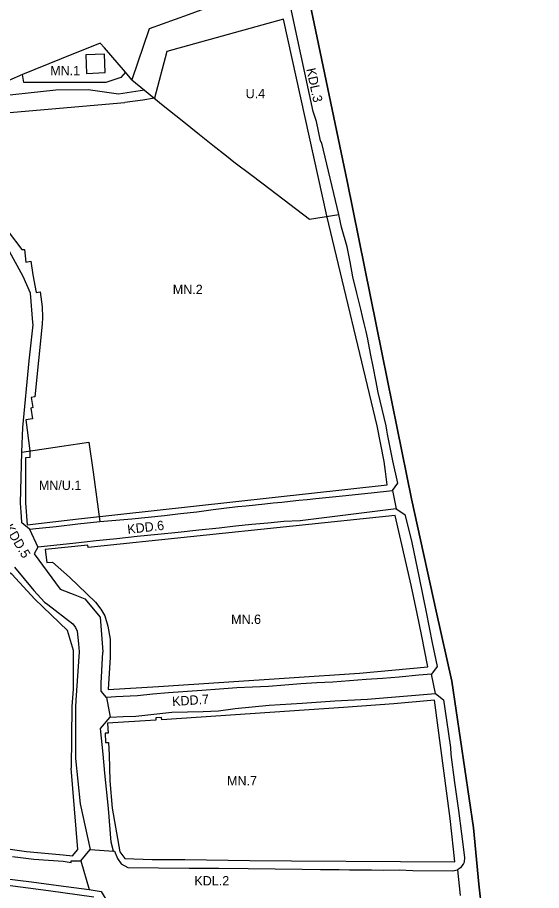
# Model space of a CAD drawing. Extents: x 7423274 to 7424514, y 5542390 to 5544261.
# Drawn here: x 7424007.3 to 7424231.1, y 5543609.4 to 5543982.5 of the extents above; entities that cross this region are included whole.
import ezdxf

# ---------------------------------------------------------------- set-up
doc = ezdxf.new("R2010")
doc.units = 0
for name, color, linetype in [('granica obszaru objętego planem', 7, 'Continuous'), ('LIN_Granica Planu', 7, 'Continuous'), ('linie rozgraniczające tereny o różnym przeznaczeniu lub różnych zasadach zagospodarowania', 7, 'Continuous'), ('nieprzekraczalna linia zabudowy', 7, 'Continuous'), ('oznaczenia terenów', 7, 'Continuous')]:
    doc.layers.add(name, color=color, linetype=linetype)

msp = doc.modelspace()

# ---------------------------------------------------------------- linework, layer by layer
at = {"layer": 'granica obszaru objętego planem'}
for p, q in [((7424131.7, 5543990.87), (7424133.97, 5543980.01)), ((7424133.97, 5543980.01), (7424148.11, 5543912.49)), ((7424148.11, 5543912.49), (7424163.08, 5543838.56)), ((7424163.08, 5543838.56), (7424169.46, 5543807.01)), ((7424169.46, 5543807.01), (7424175.57, 5543776.81)), ((7424175.57, 5543776.81), (7424186.15, 5543728.82)), ((7424186.15, 5543728.82), (7424192.74, 5543698.89)), ((7424204.36, 5543612.15), (7424228.15, 5543398.17))]:
    msp.add_line(p, q, dxfattribs=at)
msp.add_lwpolyline([(7424192.74, 5543698.89), (7424202.07, 5543636.25), (7424204.36, 5543612.15)], dxfattribs=at)
at = {"layer": 'LIN_Granica Planu'}
for p, q in [((7424133.97, 5543980.01), (7424131.7, 5543990.87)), ((7424148.11, 5543912.49), (7424133.97, 5543980.01)), ((7424163.08, 5543838.56), (7424148.11, 5543912.49)), ((7424169.46, 5543807.01), (7424163.08, 5543838.56)), ((7424175.57, 5543776.81), (7424169.46, 5543807.01)), ((7424186.15, 5543728.82), (7424175.57, 5543776.81)), ((7424192.74, 5543698.89), (7424186.15, 5543728.82)), ((7424228.15, 5543398.17), (7424204.36, 5543612.15))]:
    msp.add_line(p, q, dxfattribs=at)
msp.add_lwpolyline([(7424204.36, 5543612.15), (7424202.07, 5543636.25), (7424192.74, 5543698.89)], dxfattribs=at)
at = {"layer": 'linie rozgraniczające tereny o różnym przeznaczeniu lub różnych zasadach zagospodarowania'}
for p, q in [((7424167.46, 5543780.3), (7424169.1, 5543772.52)), ((7424012.43, 5543763.83), (7424016.04, 5543756.19)), ((7424045.38, 5543691.93), (7424046.98, 5543683.5)), ((7424034.43, 5543622.13), (7424038.33, 5543626.9)), ((7424038.33, 5543626.9), (7424048.4, 5543626.15)), ((7424034.43, 5543622.13), (7424037.96, 5543609.76)), ((7424195.16, 5543618.28), (7424196.31, 5543607.23))]:
    msp.add_line(p, q, dxfattribs=at)
for points in [[(7424129.39, 5544001.9), (7424129.8, 5543999.91), (7424131.7, 5543990.87), (7424133.97, 5543980.01), (7424148.11, 5543912.49), (7424163.08, 5543838.56), (7424169.46, 5543807.01), (7424175.57, 5543776.81), (7424186.15, 5543728.82), (7424192.74, 5543698.89), (7424202.07, 5543636.25), (7424204.36, 5543612.15), (7424228.15, 5543398.17), (7424228.51, 5543394.73), (7424242.62, 5543256.86), (7424248.04, 5543257.08)], [(7424121.12, 5543998.85), (7424109.29, 5543994.26), (7424106.54, 5543993.26), (7424101.71, 5543991.49), (7424096.89, 5543989.71), (7424080.24, 5543983.67), (7424063.58, 5543977.62), (7424056.19, 5543955.82)], [(7424144.55, 5543898.27), (7424137.31, 5543928.84), (7424136.75, 5543929.79), (7424134.98, 5543938), (7424133.54, 5543942.33), (7424128.46, 5543966.1), (7424122.6, 5543993.46), (7424121.12, 5543998.85)], [(7424053.47, 5543959.08), (7424044.49, 5543969.61), (7424042.6, 5543971.47), (7424026.04, 5543964.79), (7424009.49, 5543958.12)], [(7424053.47, 5543959.08), (7424051.5, 5543956.89), (7424045.13, 5543954.76), (7424027.61, 5543954.73), (7424010.09, 5543954.7), (7424009.49, 5543958.12)], [(7424056.19, 5543955.82), (7424053.47, 5543959.08)], [(7424009.49, 5543958.12), (7424003.59, 5543955.61), (7423997.7, 5543953.09), (7423992.95, 5543951.78), (7423988.2, 5543950.47), (7423983.6, 5543948.86), (7423979, 5543947.24), (7423974.12, 5543945.83), (7423962.62, 5543942.75), (7423956.01, 5543941.1), (7423942.79, 5543937.91), (7423929.57, 5543934.71), (7423925.31, 5543933.4), (7423921.74, 5543931.7), (7423920.97, 5543931.26)], [(7424056.19, 5543955.82), (7424061.6, 5543951.39)], [(7424061.6, 5543951.39), (7424050.54, 5543949.78), (7424037.51, 5543951.62), (7424023.67, 5543951.43), (7424011.93, 5543950.16), (7424001.33, 5543948.98), (7423995.7, 5543948.35), (7423987.33, 5543944.28), (7423981.88, 5543941.81), (7423950.16, 5543934.53), (7423925.71, 5543928.9), (7423925.33, 5543927.63), (7423925.33, 5543927.61), (7423925.32, 5543927.6), (7423925.28, 5543927.6)], [(7424061.6, 5543951.39), (7424069.62, 5543944.95), (7424077.63, 5543938.51), (7424085.03, 5543932.56), (7424090.79, 5543927.96), (7424096.55, 5543923.36), (7424099.78, 5543920.77), (7424107.52, 5543914.96), (7424115.25, 5543909.14), (7424123.62, 5543902.75), (7424131.99, 5543896.36), (7424138.27, 5543897.32), (7424144.55, 5543898.27)], [(7424009.26, 5543796.75), (7424009.59, 5543807.35), (7424012.28, 5543835.77), (7424014.01, 5543851.2), (7424013.93, 5543852.09), (7424012.86, 5543864.73), (7424009.71, 5543871.85), (7424004, 5543882.5), (7423992.6, 5543894.18), (7423987.31, 5543898.3), (7423984.61, 5543899.85), (7423973.32, 5543904.78), (7423938.39, 5543918.19), (7423926.52, 5543923.51), (7423925.07, 5543926.76), (7423925.28, 5543927.6)], [(7424167.46, 5543780.3), (7424169.79, 5543783.54), (7424167.62, 5543793.09), (7424165.29, 5543804.44), (7424165.04, 5543806.21), (7424164.8, 5543807.99), (7424161.42, 5543822.2), (7424160.36, 5543827.44), (7424159.3, 5543832.67), (7424158.15, 5543838.86), (7424157, 5543845.04), (7424156.21, 5543848.36), (7424155.41, 5543851.67), (7424154.67, 5543854.73), (7424153.94, 5543857.79), (7424152.24, 5543864.71), (7424150.53, 5543871.63), (7424149.33, 5543878.09), (7424148.12, 5543884.55), (7424145.68, 5543892.86), (7424144.55, 5543898.27)], [(7424009.26, 5543796.75), (7424026.29, 5543799.32), (7424037.82, 5543801.07), (7424039.6, 5543788.22), (7424041.04, 5543777.69), (7424042.47, 5543767.15)], [(7424012.43, 5543763.83), (7424009.19, 5543766.54), (7424009, 5543769.26), (7424008.58, 5543775.01), (7424009.26, 5543796.75)], [(7424042.47, 5543767.15), (7424049.32, 5543767.73), (7424056.17, 5543768.31), (7424063.11, 5543769.01), (7424070.05, 5543769.72), (7424076.99, 5543770.51), (7424083.92, 5543771.3), (7424090.84, 5543772.19), (7424097.77, 5543773.07), (7424101.4, 5543773.45), (7424105.03, 5543773.83), (7424108.98, 5543774.24), (7424112.93, 5543774.65), (7424116.56, 5543775.03), (7424120.19, 5543775.41), (7424123.82, 5543775.79), (7424127.45, 5543776.16), (7424131.08, 5543776.54), (7424134.71, 5543776.92), (7424140.43, 5543777.51), (7424146.15, 5543778.11), (7424158.3, 5543779.36), (7424167.46, 5543780.3)], [(7424169.1, 5543772.52), (7424128.11, 5543767.46), (7424121.04, 5543767.13), (7424114.2, 5543766.46), (7424107.36, 5543765.79), (7424100.41, 5543765.04), (7424093.46, 5543764.3), (7424084.71, 5543763.38), (7424075.97, 5543762.47), (7424067.21, 5543761.55), (7424058.46, 5543760.64), (7424049.71, 5543759.73), (7424040.96, 5543758.81), (7424035.96, 5543758.29), (7424030.97, 5543757.76), (7424016.04, 5543756.19)], [(7424169.1, 5543772.52), (7424172.72, 5543770.15), (7424173.85, 5543765.62), (7424175.7, 5543758.17), (7424177.25, 5543750.58), (7424178.79, 5543742.98), (7424181.78, 5543728.31), (7424184.45, 5543715.25), (7424186.51, 5543705.14), (7424184.11, 5543701.89)], [(7424012.43, 5543763.83), (7424016.61, 5543764.26), (7424023.81, 5543765.01), (7424033.14, 5543766.08), (7424042.47, 5543767.15)], [(7424016.04, 5543756.19), (7424014.43, 5543753.22), (7424025.52, 5543738.19), (7424031.86, 5543735.73), (7424036.13, 5543734.08), (7424042.68, 5543726.25), (7424043.77, 5543711.35)], [(7424006.1, 5543747.6), (7424014.31, 5543737.6), (7424018.89, 5543732.62), (7424020.25, 5543731.58), (7424031, 5543723.4), (7424032.09, 5543721.82), (7424032.78, 5543720.24), (7424033.42, 5543714.89), (7424033.72, 5543711.43), (7424032.26, 5543690.72), (7424032.15, 5543687.75), (7424032.14, 5543665.88), (7424034.16, 5543646.49), (7424038.33, 5543626.9)], [(7424045.38, 5543691.93), (7424043.11, 5543694.66), (7424043.14, 5543697.97), (7424043.77, 5543711.24)], [(7424043.76, 5543711.35), (7424043.77, 5543711.24)], [(7424043.77, 5543711.35), (7424043.77, 5543711.24)], [(7424184.11, 5543701.89), (7424178.68, 5543701.37), (7424170.25, 5543700.55), (7424163.25, 5543700.05), (7424156.24, 5543699.55), (7424149.12, 5543699.02), (7424141.99, 5543698.49), (7424135.17, 5543698.09), (7424128.35, 5543697.69), (7424121.44, 5543697.11), (7424114.52, 5543696.53), (7424107.76, 5543696.28), (7424101, 5543696.02), (7424093.55, 5543695.46), (7424086.1, 5543694.91), (7424071.79, 5543693.85), (7424065.17, 5543693.25), (7424058.56, 5543692.66), (7424049.29, 5543692.12), (7424045.38, 5543691.93)], [(7424185.8, 5543693.62), (7424184.11, 5543701.89)], [(7424046.98, 5543683.5), (7424052.41, 5543683.7), (7424057.83, 5543683.89), (7424065.51, 5543684.72), (7424073.19, 5543685.55), (7424079.9, 5543685.75), (7424086.6, 5543685.96), (7424093.11, 5543686.17), (7424100.35, 5543687.16), (7424107.57, 5543687.9), (7424114.79, 5543688.64), (7424128.88, 5543689.51), (7424142.81, 5543690.39), (7424156.75, 5543691.22), (7424170.42, 5543692.3), (7424185.8, 5543693.62)], [(7424185.8, 5543693.62), (7424189.23, 5543690.91), (7424190.53, 5543682.18), (7424192.27, 5543670.48), (7424192.38, 5543667.53), (7424193.99, 5543655.56), (7424195.6, 5543643.59), (7424196.88, 5543633.58), (7424198.17, 5543623.57), (7424198.09, 5543621.51), (7424197.8, 5543620.87), (7424196.51, 5543619.05), (7424195.16, 5543618.28)], [(7424048.4, 5543626.15), (7424047.38, 5543630.11), (7424046.14, 5543644.41), (7424044.69, 5543659.51), (7424043.99, 5543667.73), (7424042.82, 5543678.7), (7424046.98, 5543683.5)], [(7424005.18, 5543623.99), (7424014.28, 5543622.79), (7424020.58, 5543622.35), (7424026.87, 5543621.91), (7424030.26, 5543621.38), (7424030.33, 5543622.09), (7424034.43, 5543622.13)], [(7424048.4, 5543626.15), (7424048.75, 5543626.21), (7424050.01, 5543623.14), (7424051.64, 5543620.81), (7424054.53, 5543619.28), (7424067.57, 5543619.15), (7424080.6, 5543619.01), (7424093.25, 5543618.88), (7424105.91, 5543618.75), (7424117.38, 5543618.63), (7424128.85, 5543618.51), (7424136.76, 5543618.42), (7424144.67, 5543618.34), (7424149.07, 5543618.29), (7424153.47, 5543618.23), (7424158.46, 5543618.17), (7424163.46, 5543618.12), (7424170.32, 5543618.16), (7424176.1, 5543617.96), (7424193.29, 5543617.86), (7424195.16, 5543618.28)], [(7424054.53, 5543619.28), (7424054.53, 5543619.28)], [(7424001.65, 5543614.58), (7424013.28, 5543613.04), (7424024.91, 5543611.49), (7424031.44, 5543610.62), (7424037.96, 5543609.76)], [(7424037.96, 5543609.76), (7424043.11, 5543608.99), (7424044.74, 5543606.11), (7424046.74, 5543601.68), (7424048.53, 5543597), (7424049.9, 5543593.66)]]:
    msp.add_lwpolyline(points, dxfattribs=at)
at = {"layer": 'nieprzekraczalna linia zabudowy'}
for p, q in [((7424139.5, 5543897.79), (7424120.89, 5543981.86)), ((7424044.46, 5543966.91), (7424036.52, 5543966.55)), ((7424036.52, 5543966.55), (7424036.88, 5543958.64)), ((7424044.83, 5543959.01), (7424044.46, 5543966.91)), ((7424036.88, 5543958.64), (7424044.83, 5543959.01)), ((7424163.96, 5543792.72), (7424160.98, 5543807.93)), ((7424164.5, 5543788.52), (7424163.96, 5543792.72)), ((7424165.23, 5543782.83), (7424164.5, 5543788.52)), ((7424051.02, 5543625.94), (7424053.16, 5543623.07))]:
    msp.add_line(p, q, dxfattribs=at)
for points in [[(7424120.89, 5543981.86), (7424071.1, 5543967.94), (7424065.86, 5543947.97)], [(7424065.86, 5543947.97), (7424065.86, 5543947.97), (7424060.91, 5543947.25), (7424053.23, 5543946.13)], [(7424053.24, 5543946.06), (7424053.24, 5543946.06), (7424053.24, 5543946.06), (7424053.24, 5543946.06), (7423982.54, 5543939.91), (7423960.7, 5543934.36)], [(7423950.39, 5543919.32), (7423963.48, 5543914.06), (7423967.18, 5543912.57), (7423970.64, 5543911.16), (7423976.27, 5543908.88), (7423981.11, 5543906.98), (7423985.86, 5543904.69), (7423988.77, 5543903.12), (7423991.47, 5543901.48), (7423993.9, 5543899.86), (7423996.01, 5543898.27), (7423998.22, 5543896.33), (7424000.76, 5543893.82), (7424003.4, 5543891), (7424009.18, 5543883.33), (7424009.18, 5543883.33), (7424010.28, 5543883.42), (7424010.92, 5543877.97), (7424013, 5543878.3), (7424013.93, 5543872.51), (7424015.35, 5543865.04), (7424017.04, 5543865.32), (7424017.82, 5543858.83), (7424018.03, 5543854.34)], [(7424160.98, 5543807.93), (7424139.5, 5543897.79), (7424139.5, 5543897.79), (7424139.5, 5543897.79)], [(7424018.03, 5543854.34), (7424017.95, 5543851.41), (7424014.81, 5543820.41)], [(7424014.81, 5543820.41), (7424013.16, 5543820.11), (7424013.88, 5543815.76), (7424013.04, 5543815.59), (7424013.82, 5543810.96), (7424010.91, 5543810.52), (7424012.58, 5543797.24)], [(7424012.58, 5543797.24), (7424012.55, 5543794.42), (7424010.75, 5543794.25), (7424010.78, 5543775.14), (7424011.41, 5543765.69)], [(7424011.41, 5543765.69), (7424033.44, 5543768.26), (7424165.23, 5543782.83)], [(7424168.61, 5543769.66), (7424037.5, 5543756.04), (7424037.37, 5543756.92)], [(7424182.6, 5543704.96), (7424179.8, 5543718.84), (7424177.97, 5543727.84), (7424175.39, 5543739.93), (7424168.61, 5543769.66)], [(7424037.37, 5543756.92), (7424037.37, 5543756.92), (7424019.23, 5543755.11)], [(7424019.23, 5543755.11), (7424019.82, 5543749.54), (7424022.31, 5543749.74), (7424029.52, 5543743.26), (7424040.7, 5543732.62), (7424042.95, 5543729.69), (7424044.64, 5543726.76), (7424045.95, 5543722.32), (7424046.97, 5543716.83), (7424046.88, 5543709.16), (7424046.09, 5543695.27)], [(7424028.68, 5543720.51), (7424014.7, 5543733.87), (7424004.92, 5543744.63), (7424003.52, 5543745.44)], [(7424031.21, 5543695.46), (7424031.21, 5543711.91), (7424028.68, 5543720.51)], [(7424046.09, 5543695.27), (7424067.6, 5543696.63), (7424123.28, 5543700.24), (7424153.32, 5543702.22), (7424182.6, 5543704.96)], [(7424030.37, 5543661.69), (7424030.71, 5543687.98), (7424031.21, 5543695.46)], [(7424185.46, 5543690.76), (7424168.07, 5543689.2), (7424146.57, 5543687.62), (7424068.91, 5543682.37)], [(7424194.09, 5543621.69), (7424193.51, 5543627.08), (7424192.14, 5543640.18), (7424185.46, 5543690.76)], [(7424066.43, 5543682.25), (7424045.77, 5543680.94)], [(7424068.91, 5543682.37), (7424068.86, 5543683.3), (7424066.38, 5543683.17), (7424066.43, 5543682.25)], [(7424045.77, 5543680.94), (7424046.01, 5543676.67), (7424044.77, 5543676.6), (7424044.99, 5543672.61), (7424046.26, 5543672.68), (7424046.55, 5543667.36)], [(7424046.56, 5543667.42), (7424046.71, 5543656.21)], [(7424026.85, 5543624.64), (7424030.85, 5543624.21), (7424033.07, 5543626.99), (7424030.22, 5543661.65)], [(7424046.71, 5543656.21), (7424047.76, 5543644.59), (7424051.02, 5543625.94)], [(7423837.7, 5543649.44), (7423872.04, 5543646.02), (7424011.15, 5543626.09), (7424026.85, 5543624.64)], [(7424039.93, 5543606.59), (7424020.52, 5543609.24), (7423987.89, 5543613.53), (7423960.85, 5543617.16), (7423923.09, 5543622.46), (7423913.13, 5543624.02), (7423890.12, 5543627.03)], [(7424053.16, 5543623.07), (7424064.89, 5543622.65), (7424069.82, 5543622.62), (7424078.85, 5543622.68), (7424106.5, 5543622.21), (7424124.31, 5543622.12), (7424170.95, 5543621.83), (7424194.09, 5543621.69)]]:
    msp.add_lwpolyline(points, dxfattribs=at)

# ---------------------------------------------------------------- texts
at = {"layer": 'oznaczenia terenów'}
for s, p in [('MN.1', (7424021.31, 5543957.84)), ('U.4', (7424104.78, 5543948.01)), ('MN.2', (7424073.66, 5543864.29)), ('MN/U.1', (7424016.48, 5543780.6)), ('MN.6', (7424098.56, 5543723.32)), ('MN.7', (7424096.83, 5543654.28)), ('KDL.2', (7424082.88, 5543611.55))]:
    msp.add_text(s, height=4, dxfattribs=at).set_placement(p)
for s, rotation, p in [('KDL.3', 282.2952, (7424130.63, 5543960.45)), ('KDD.5', 300.9466, (7424001.62, 5543764.52)), ('KDD.6', 6.6217, (7424054.48, 5543761.76)), ('KDD.7', 3.7402, (7424073.5, 5543688.2))]:
    msp.add_text(s, height=4, rotation=rotation, dxfattribs=at).set_placement(p)

doc.saveas('drawing.dxf')
